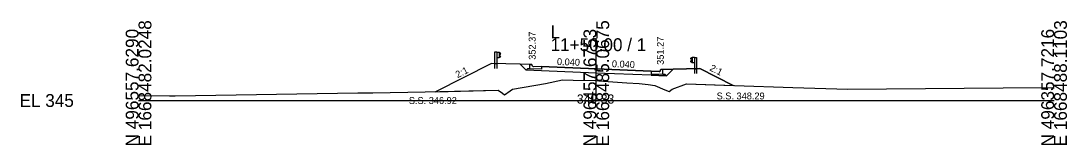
# Model space of a CAD drawing. Extents: x -26 to 203, y -10 to 5517.
# Drawn here: x -25.7 to 202.8, y 1490.3 to 1517.3 of the extents above; entities that cross this region are included whole.
import ezdxf

# ---------------------------------------------------------------- set-up
doc = ezdxf.new("R2010")
doc.units = 0
for name, color, linetype in [('Exist Cross Section Cell', 7, 'Continuous'), ('Exist XS Center Line Elevation Label', 7, 'Continuous'), ('Exist XS Ground Line', 7, 'Continuous'), ('Prop XS Earthwork Shape', 7, 'Continuous'), ('Prop XS Finish Grade', 7, 'Continuous'), ('Prop XS Finish Grade CurbGutter', 7, 'Continuous'), ('Prop XS Finish Grade Earthwork', 7, 'Continuous'), ('Prop XS Finish Grade Pavement', 7, 'Continuous'), ('Prop XS Geopak Shape', 7, 'Continuous'), ('Prop XS Hydro Elevations', 7, 'Continuous'), ('Prop XS Pvmt Edge Slope', 7, 'Continuous'), ('Prop XS SE Text', 7, 'Continuous'), ('Prop XS Side Slope Text', 7, 'Continuous'), ('Prop XS SS Elevation Text', 7, 'Continuous'), ('Prop XS Subgrade CurbGutter', 7, 'Continuous'), ('Prop XS Subgrade Earthwork', 7, 'Continuous'), ('Typical Guardrail CELL', 7, 'Continuous')]:
    doc.layers.add(name, color=color, linetype=linetype)

msp = doc.modelspace()

# ---------------------------------------------------------------- linework, layer by layer
at = {"layer": 'Exist Cross Section Cell'}
for p, q in [((100, 1500), (100, 1513.56)), ((0, 1500), (100, 1500)), ((100, 1500), (200, 1500))]:
    msp.add_line(p, q, dxfattribs=at)
at = {"layer": 'Exist XS Ground Line'}
for p, q in [((88.9, 1503.74), (92.65, 1504.52)), ((92.65, 1504.52), (94.97, 1504.47)), ((94.97, 1504.47), (100, 1504.33)), ((100, 1504.33), (100.54, 1504.31)), ((100.54, 1504.31), (106.68, 1503.88)), ((106.68, 1503.88), (109.35, 1503.68)), ((7.97, 1500.99), (47.94, 1501.64)), ((47.94, 1501.64), (50.13, 1501.65)), ((50.13, 1501.65), (51.15, 1501.69)), ((51.15, 1501.69), (62.58, 1501.87)), ((62.58, 1501.87), (78.54, 1502.23)), ((78.54, 1502.23), (79.52, 1501.57)), ((79.52, 1501.57), (79.95, 1501.26)), ((79.95, 1501.26), (81.15, 1502.11)), ((81.15, 1502.11), (81.7, 1502.49)), ((81.7, 1502.49), (88.9, 1503.74)), ((109.35, 1503.68), (111.32, 1503.47)), ((111.32, 1503.47), (112.75, 1503.27)), ((112.75, 1503.27), (115, 1502.31)), ((115, 1502.31), (115.91, 1501.95)), ((115.91, 1501.95), (116.59, 1502.48)), ((116.59, 1502.48), (119.68, 1503.67)), ((119.68, 1503.67), (130.18, 1503.28)), ((130.18, 1503.28), (142.94, 1502.84)), ((142.94, 1502.84), (154.95, 1502.46)), ((154.95, 1502.46), (197.31, 1502.84)), ((197.31, 1502.84), (200, 1502.8)), ((0, 1501.07), (6.74, 1500.99)), ((6.74, 1500.99), (7.97, 1500.99))]:
    msp.add_line(p, q, dxfattribs=at)
at = {"layer": 'Prop XS Earthwork Shape'}
msp.add_lwpolyline([(83.36, 1507.91), (77.1, 1508.04), (64.87, 1501.92), (78.54, 1502.23), (79.52, 1501.57), (79.95, 1501.26), (81.15, 1502.11), (81.7, 1502.49), (88.9, 1503.74), (92.65, 1504.52), (94.97, 1504.47), (100, 1504.33), (100.54, 1504.31), (106.68, 1503.88), (109.35, 1503.68), (111.32, 1503.47), (112.75, 1503.27), (115, 1502.31), (115.91, 1501.95), (116.59, 1502.48), (119.68, 1503.67), (129.89, 1503.29), (122.6, 1506.94), (116.77, 1506.81), (115.33, 1505.38), (112, 1505.51), (100, 1505.99), (88, 1506.47), (84.67, 1506.61)], close=True, dxfattribs=at)
at = {"layer": 'Prop XS Finish Grade'}
for p, q in [((85.5, 1507.87), (83.36, 1507.91)), ((114.5, 1506.77), (116.77, 1506.81))]:
    msp.add_line(p, q, dxfattribs=at)
at = {"layer": 'Prop XS Finish Grade CurbGutter'}
for p, q in [((85.5, 1507.87), (85.75, 1507.87)), ((85.75, 1507.87), (85.88, 1507.83)), ((85.97, 1507.73), (85.88, 1507.83)), ((86.03, 1507.48), (85.97, 1507.73)), ((86.13, 1507.39), (86.03, 1507.48)), ((86.25, 1507.37), (86.13, 1507.39)), ((88, 1507.39), (86.25, 1507.37)), ((112, 1506.43), (113.75, 1506.29)), ((113.75, 1506.29), (113.87, 1506.31)), ((113.87, 1506.31), (113.97, 1506.4)), ((113.97, 1506.4), (114.03, 1506.65)), ((114.03, 1506.65), (114.12, 1506.74)), ((114.25, 1506.77), (114.12, 1506.74)), ((114.5, 1506.77), (114.25, 1506.77))]:
    msp.add_line(p, q, dxfattribs=at)
at = {"layer": 'Prop XS Finish Grade Earthwork'}
for p, q in [((77.11, 1508.05), (64.87, 1501.92)), ((83.36, 1507.91), (77.1, 1508.04)), ((116.77, 1506.81), (122.6, 1506.94)), ((122.6, 1506.94), (129.89, 1503.29))]:
    msp.add_line(p, q, dxfattribs=at)
at = {"layer": 'Prop XS Finish Grade Pavement'}
for p, q in [((88, 1507.39), (100, 1506.91)), ((100, 1506.91), (112, 1506.43))]:
    msp.add_line(p, q, dxfattribs=at)
at = {"layer": 'Prop XS Geopak Shape'}
msp.add_lwpolyline([(64.87, 1501.92), (78.54, 1502.23), (79.52, 1501.57), (79.95, 1501.26), (81.15, 1502.11), (81.7, 1502.49), (88.9, 1503.74), (92.65, 1504.52), (94.97, 1504.47), (100, 1504.33), (100.54, 1504.31), (106.68, 1503.88), (109.35, 1503.68), (111.32, 1503.47), (112.75, 1503.27), (115, 1502.31), (115.91, 1501.95), (116.59, 1502.48), (119.68, 1503.67), (129.89, 1503.29), (122.6, 1506.94), (116.77, 1506.81), (114.5, 1506.77), (114.25, 1506.77), (114.12, 1506.74), (114.03, 1506.65), (113.97, 1506.4), (113.87, 1506.31), (113.75, 1506.29), (112, 1506.43), (100, 1506.91), (88, 1507.39), (86.25, 1507.37), (86.13, 1507.39), (86.03, 1507.48), (85.97, 1507.73), (85.88, 1507.83), (85.75, 1507.87), (85.5, 1507.87), (83.36, 1507.91), (77.1, 1508.04)], close=True, dxfattribs=at)
at = {"layer": 'Prop XS Pvmt Edge Slope'}
for p, q in [((85, 1506.93), (84.67, 1506.61)), ((85.5, 1506.91), (85, 1506.93)), ((114.5, 1505.75), (115, 1505.73)), ((115, 1505.73), (115.33, 1505.38))]:
    msp.add_line(p, q, dxfattribs=at)
at = {"layer": 'Prop XS Subgrade CurbGutter'}
for p, q in [((85.5, 1506.91), (85.5, 1507.87)), ((88, 1506.81), (85.5, 1506.91)), ((88, 1507.39), (88, 1506.81)), ((112, 1506.43), (112, 1505.85)), ((114.5, 1505.75), (114.5, 1506.77)), ((112, 1505.85), (114.5, 1505.75))]:
    msp.add_line(p, q, dxfattribs=at)
at = {"layer": 'Prop XS Subgrade Earthwork'}
for p, q in [((84.67, 1506.61), (83.36, 1507.91)), ((88, 1506.47), (84.67, 1506.61)), ((88, 1506.47), (88, 1506.47)), ((100, 1505.99), (88, 1506.47)), ((115.33, 1505.38), (116.77, 1506.81)), ((112, 1505.51), (100, 1505.99)), ((112, 1505.51), (112, 1505.51)), ((112, 1505.51), (115.33, 1505.38))]:
    msp.add_line(p, q, dxfattribs=at)
at = {"layer": 'Typical Guardrail CELL'}
for p, q in [((78.28, 1510.5), (77.79, 1510.5)), ((77.79, 1510.5), (77.79, 1508.02)), ((78.28, 1510.5), (78.28, 1508.02)), ((78.28, 1510.5), (78.78, 1510.5)), ((78.28, 1509.34), (78.78, 1509.34)), ((78.78, 1510.5), (78.78, 1509.34)), ((78.78, 1510.5), (79.07, 1510.3)), ((78.78, 1509.97), (79.07, 1510.17)), ((78.78, 1509.92), (78.78, 1509.97)), ((78.78, 1509.92), (78.78, 1509.88)), ((78.78, 1509.88), (79.07, 1509.68)), ((78.78, 1509.34), (79.07, 1509.55)), ((120.93, 1509.4), (120.64, 1509.2)), ((120.93, 1508.87), (120.64, 1509.07)), ((120.93, 1508.77), (120.64, 1508.57)), ((120.93, 1508.24), (120.64, 1508.44)), ((121.43, 1509.4), (120.93, 1509.4)), ((120.93, 1509.4), (120.93, 1508.24)), ((120.93, 1508.82), (120.93, 1508.87)), ((120.93, 1508.82), (120.93, 1508.77)), ((121.43, 1509.4), (121.43, 1506.91)), ((121.43, 1509.4), (121.92, 1509.4)), ((121.92, 1509.4), (121.92, 1506.91)), ((78.28, 1508.02), (77.79, 1508.02)), ((77.79, 1508.02), (77.79, 1507.01)), ((78.28, 1508.02), (78.28, 1507.01)), ((121.43, 1508.24), (120.93, 1508.24)), ((121.43, 1506.91), (121.92, 1506.91)), ((121.43, 1506.91), (121.43, 1505.9)), ((121.92, 1506.91), (121.92, 1505.9))]:
    msp.add_line(p, q, dxfattribs=at)
for centre, start, end in [((79.03, 1510.24), 304.9888, 54.997), ((79.03, 1509.61), 304.9634, 54.9941), ((120.68, 1509.13), 125.003, 235.0112), ((120.68, 1508.51), 125.0059, 235.0366)]:
    msp.add_arc(centre, 0.0776, start, end, dxfattribs=at)

# ---------------------------------------------------------------- texts
at = {"layer": 'Exist Cross Section Cell'}
for s, p in [('N 496557.6290', (0, 1490)), ('E 1668482.0248', (2.8, 1490)), ('N 496457.6753', (100, 1490)), ('E 1668485.0675', (102.8, 1490)), ('N 496357.7216', (200, 1490)), ('E 1668488.1103', (202.8, 1490))]:
    msp.add_text(s, height=2.8, rotation=90, dxfattribs=at).set_placement(p)
for s, p in [('L', (90, 1513.56)), ('11+50.00 / 1', (90, 1510.76)), ('EL 345', (-26, 1498.6))]:
    msp.add_text(s, height=2.8, dxfattribs=at).set_placement(p)
at = {"layer": 'Exist XS Center Line Elevation Label'}
msp.add_text('349.33', height=2, dxfattribs=at).set_placement((95.75, 1499.33))
at = {"layer": 'Prop XS Hydro Elevations'}
for s, p in [('352.37', (86.75, 1508.87)), ('351.27', (114.75, 1507.77))]:
    msp.add_text(s, height=1.5, rotation=90, dxfattribs=at).set_placement(p)
at = {"layer": 'Prop XS SE Text'}
for p in [(91.38, 1507.75), (103.38, 1507.27)]:
    msp.add_text('0.040', height=1.5, rotation=357.7094, dxfattribs=at).set_placement(p)
at = {"layer": 'Prop XS Side Slope Text'}
for rotation, p in [(26.5651, (69.69, 1504.86)), (333.4349, (124.62, 1506.61))]:
    msp.add_text('2:1', height=1.5, rotation=rotation, dxfattribs=at).set_placement(p)
at = {"layer": 'Prop XS SS Elevation Text'}
for s, p in [('S.S. 348.29', (126.29, 1500.24)), ('S.S. 346.92', (59.05, 1499.25))]:
    msp.add_text(s, height=1.5, dxfattribs=at).set_placement(p)

doc.saveas('drawing.dxf')
